(* Logix 5000 project; controller Soda_Ash vendor 1 type 14 code 92 rev 35.11; software revision 35.00; part 2 of 3 *)
(* tags used below, declared in another part *)
   C6100 : Motor_Conv_Type;   // C-6100 Soda Ash Screw Conveyor
   C6100_Aux : BOOL;   // C-6100 Soda Ash Screw Conveyor Aux. Contact
   C6100_DB : Motor_Conv;   // C-6100 Soda Ash Screw Conveyor
   C6100_HOA : BOOL;   // C-6100 Storage Pump Screw Conveyor H.O.A.
   C6100_OL : BOOL;   // C-6100 Soda Ash Screw Conveyor O. L. Trip
   C6100_Start : BOOL;   // C-6100 Soda Ash Screw Conveyor Starter
   Convey_Time : TIMER;   // Soda Ash C-6100 Conveyor Clear Timer
   FIC1000 : PID;   // Soda Ash FIC1000 Sample Flow Controller
   FIC1000_Tmr : TIMER;   // Soda Ash FIC1000 Material A Flow Controller Sample Timer
   FQI1000 : DINT;   // Soda Ash FQI1000 Sample Flow Accumulation
   FQI1000_Oper_Reset : BOOL;   // Soda Ash FQI1000 Sample Flow Accumulation Reset
   FQI1000_Tmr : TIMER;   // Soda Ash FQI1000 Sample Flow Accumulation Timer
   FT1000 : REAL;   // Soda Ash FT1000 Sample Flow
   FY1000 : REAL;   // Soda Ash FY1000 Sample Flow Control Valve
   G6000 : Gate_Slide_Type;   // G-6000 CIP Tank Slide Gate
   G6000_Close_Aux : BOOL;   // G-6000 CIP Tank Slide Gate Clos Aux Contact
   G6000_DB : Gate_Slide;   // G-6000 CIP Tank Slide Gate
   G6000_HOA : BOOL;   // G-6000 CIP Tank Slide Gate H.O.A.
   G6000_OL : BOOL;   // G-6000 CIP Tank Slide Gate O. L. Trip
   G6000_Open_Aux : BOOL;   // G-6000 CIP Tank Slide Gate Open Aux Contact
   G6000_Start_Close : BOOL;   // G-6000 CIP Tank Slide Gate Starter Close
   G6000_Start_Open : BOOL;   // G-6000 CIP Tank Slide Gate Starter Open
   G6200 : Gate_Flop_Type;   // G-6200 CIP Tank Flop Gate
   G6200_DB : Gate_Flop;   // G-6200 CIP Tank Flop Gate
   G6200_HOA : BOOL;   // G-6200 Soda Ash CIP flop Gate H.O.A.
   G6200_Sol_Left : BOOL;   // G-6200 CIP Tank Flop Gate Left Valve
   G6200_Sol_Right : BOOL;   // G-6200 CIP Tank Flop Gate Right Valve
   L6100 : Motor_Std_Type;   // L-6100 Soda Ash Airlock
   L6100_Aux : BOOL;   // L-6100 Soda Ash Airlock Aux. Contact
   L6100_DB : Motor_Std;   // L-6100 Soda Ash Airlock
   L6100_FailSdwn_Tmr : TIMER;   // L-6100 Soda Ash Airlock Fail to Shutdown Timer
   L6100_HOA : BOOL;   // L-6100 Storage Aitlock Motor H.O.A.
   L6100_Level_Sdwn_Tmr : TIMER;   // L6100 low level when Transfer Running Shutdown Timer
   L6100_OL : BOOL;   // L-6100 Soda Ash Airlock O. L. Trip
   L6100_Start : BOOL;   // L-6100 Soda Ash Airlock Starter
   Soda_Ash : Unit_Type;   // Soda Ash Unit
   Soda_Ash_EShutdown : Seq_Type;   // Soda Ash E-Shutdown
   Soda_Ash_Hold : Seq_Type;   // Soda Ash Hold
   Soda_Ash_Sdwn_from_CIP : ALIAS FOR CIP_Export_Info.11;   // Soda Ash Shutdown Request From CIP
   Soda_Ash_Shutdown : Seq_Type;   // Soda Ash Shutdown
   Soda_Ash_Start_from_CIP : ALIAS FOR CIP_Export_Info.12;   // Soda Ash Start Transfer Request From CIP
   Soda_Ash_StrtTrans : Seq_Type;   // Soda Ash Start Transfer
   SS6100 : BOOL;   // C-6100 Soda Ash Screw Conveyor Zero Speed Switch
   XV1001_CloseLS : BOOL;   // XV1001 Soda Ash Outlet Valve Closed Limit Switch
   XV1001_OpenLS : BOOL;   // XV1001 Soda Ash Outlet Valve Open Limit Switch
   XV1001_Sol_Vlv : BOOL;   // XV1001 Soda Ash Outlet Valve Solenoid
   ZSC6000 : BOOL;   // G-6000 Soda Ash CIP Slide Gate Closed LS
   ZSL6200 : BOOL;   // G-6200 Soda Ash CIP flop Gate Left LS
   ZSO6000 : BOOL;   // G-6000 Soda Ash CIP Slide Gate Open LS
   ZSR6200 : BOOL;   // G-6200 Soda Ash CIP flop Gate Right LS

PROGRAM Simulation   (* main routine Simulation *)
VAR
   Sim_Tmr_C6100_Start : TIMER := (PRE := 5000);
   Sim_Tmr_C6100_Stop : TIMER := (PRE := 5000);
   Sim_Tmr_G6000_Start : TIMER := (PRE := 5000);
   Sim_Tmr_G6000_Stop : TIMER := (PRE := 5000);
   Sim_Tmr_G6200_Left : TIMER := (PRE := 5000);
   Sim_Tmr_G6200_Right : TIMER := (PRE := 5000);
   Sim_Tmr_L6100_Start : TIMER := (PRE := 5000);
   Sim_Tmr_L6100_Stop : TIMER := (PRE := 5000);
   Sim_Tmr_XV1001_Close : TIMER := (PRE := 5000);
   Sim_Tmr_XV1001_Open : TIMER := (PRE := 5000);
END_VAR

ROUTINE Simulation   (* ladder *)
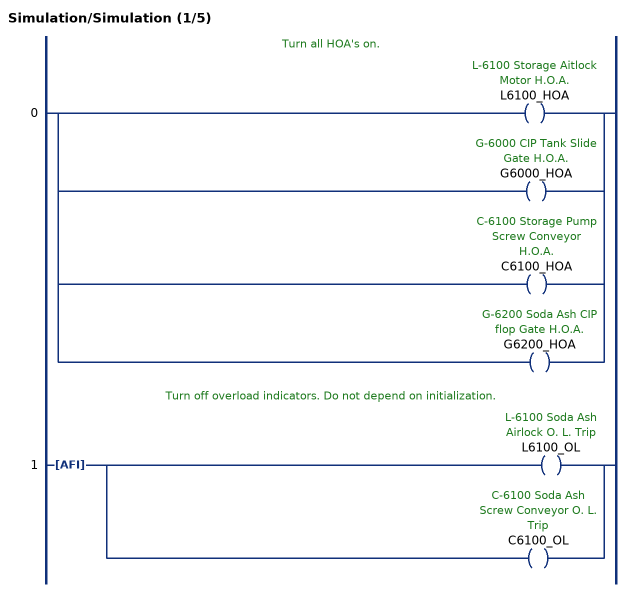
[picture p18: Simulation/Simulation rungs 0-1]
   // Turn all HOA's on.
   0: [OTE(L6100_HOA) ,OTE(G6000_HOA) ,OTE(C6100_HOA) ,OTE(G6200_HOA) ];
   // Turn off overload indicators. Do not depend on initialization.
   1: AFI()[OTE(L6100_OL) ,OTE(C6100_OL) ];
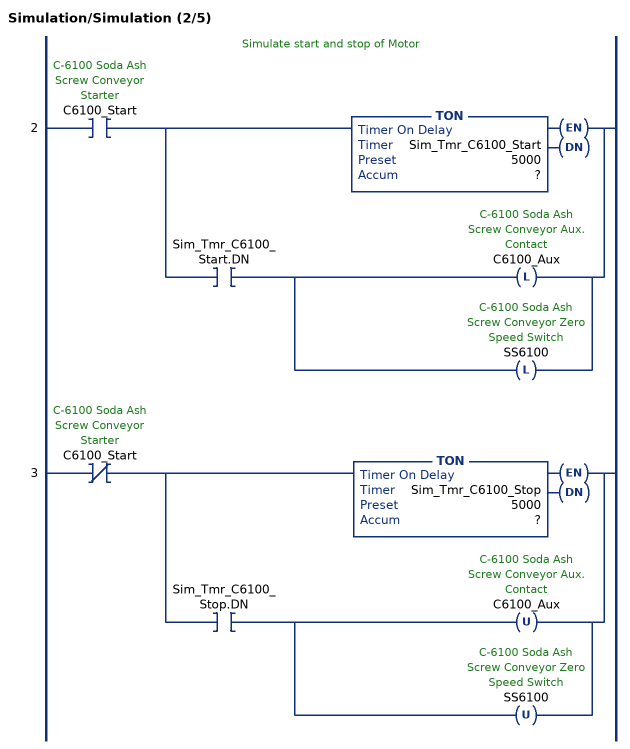
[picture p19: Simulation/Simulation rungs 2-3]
   // Simulate start and stop of Motor
   2: XIC(C6100_Start)[TON(Sim_Tmr_C6100_Start,?,?) ,XIC(Sim_Tmr_C6100_Start.DN) [OTL(C6100_Aux) ,OTL(SS6100) ] ];
   3: XIO(C6100_Start)[TON(Sim_Tmr_C6100_Stop,?,?) ,XIC(Sim_Tmr_C6100_Stop.DN) [OTU(C6100_Aux) ,OTU(SS6100) ] ];
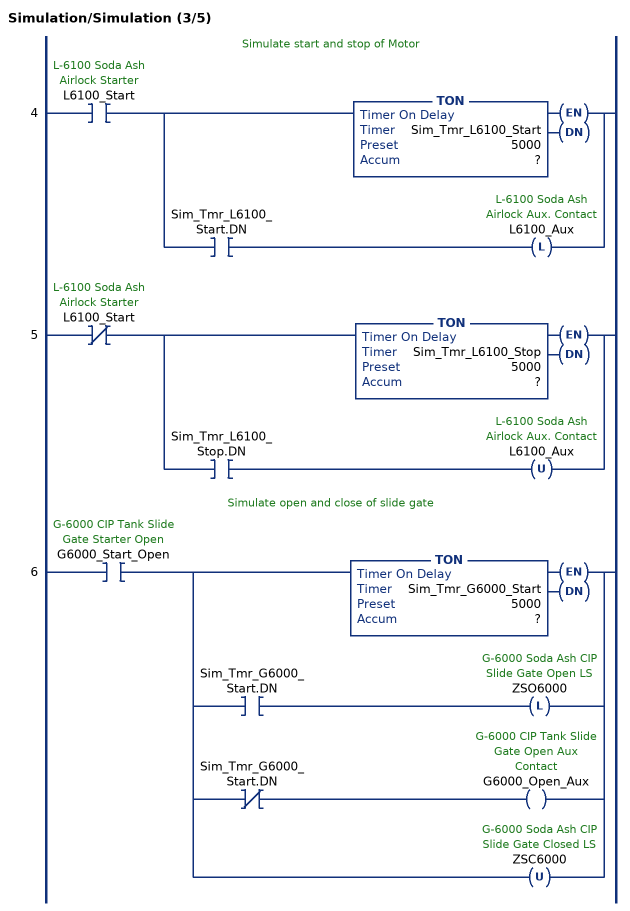
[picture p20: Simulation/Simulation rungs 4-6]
   // Simulate start and stop of Motor
   4: XIC(L6100_Start)[TON(Sim_Tmr_L6100_Start,?,?) ,XIC(Sim_Tmr_L6100_Start.DN) OTL(L6100_Aux) ];
   5: XIO(L6100_Start)[TON(Sim_Tmr_L6100_Stop,?,?) ,XIC(Sim_Tmr_L6100_Stop.DN) OTU(L6100_Aux) ];
   // Simulate open and close of slide gate
   6: XIC(G6000_Start_Open)[TON(Sim_Tmr_G6000_Start,?,?) ,XIC(Sim_Tmr_G6000_Start.DN) OTL(ZSO6000) ,XIO(Sim_Tmr_G6000_Start.DN) OTE(G6000_Open_Aux) ,OTU(ZSC6000) ];
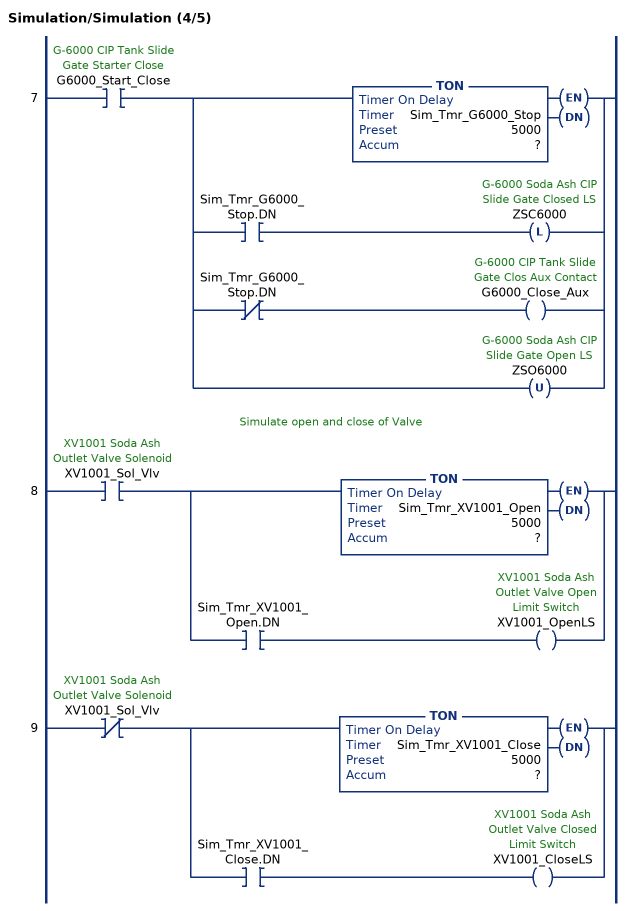
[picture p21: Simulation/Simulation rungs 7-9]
   7: XIC(G6000_Start_Close)[TON(Sim_Tmr_G6000_Stop,?,?) ,XIC(Sim_Tmr_G6000_Stop.DN) OTL(ZSC6000) ,XIO(Sim_Tmr_G6000_Stop.DN) OTE(G6000_Close_Aux) ,OTU(ZSO6000) ];
   // Simulate open and close of Valve
   8: XIC(XV1001_Sol_Vlv)[TON(Sim_Tmr_XV1001_Open,?,?) ,XIC(Sim_Tmr_XV1001_Open.DN) OTE(XV1001_OpenLS) ];
   9: XIO(XV1001_Sol_Vlv)[TON(Sim_Tmr_XV1001_Close,?,?) ,XIC(Sim_Tmr_XV1001_Close.DN) OTE(XV1001_CloseLS) ];
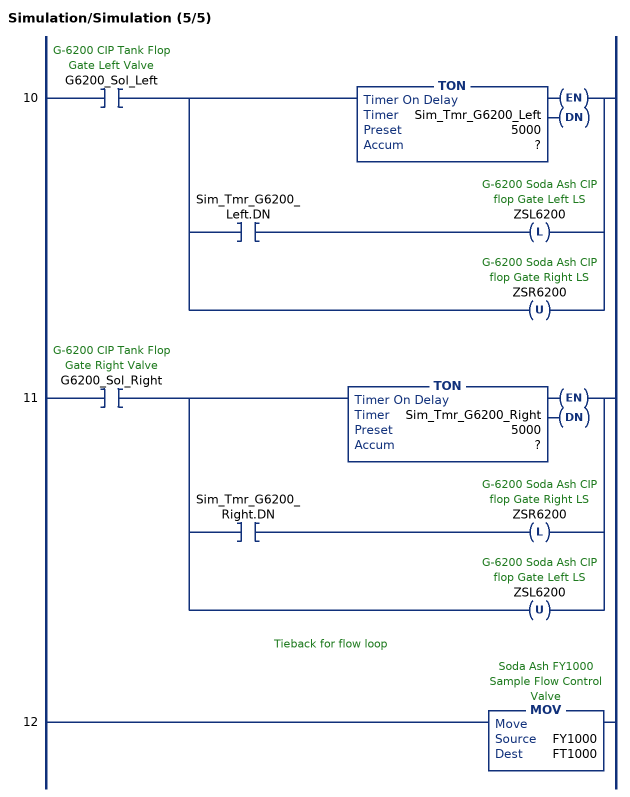
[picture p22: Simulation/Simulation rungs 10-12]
   10: XIC(G6200_Sol_Left)[TON(Sim_Tmr_G6200_Left,?,?) ,XIC(Sim_Tmr_G6200_Left.DN) OTL(ZSL6200) ,OTU(ZSR6200) ];
   11: XIC(G6200_Sol_Right)[TON(Sim_Tmr_G6200_Right,?,?) ,XIC(Sim_Tmr_G6200_Right.DN) OTL(ZSR6200) ,OTU(ZSL6200) ];
   // Tieback for flow loop
   12: MOV(FY1000,FT1000);
END_ROUTINE
END_PROGRAM

PROGRAM Soda_Ash   (* main routine MainRoutine *)

ROUTINE Gates   (* ladder *)
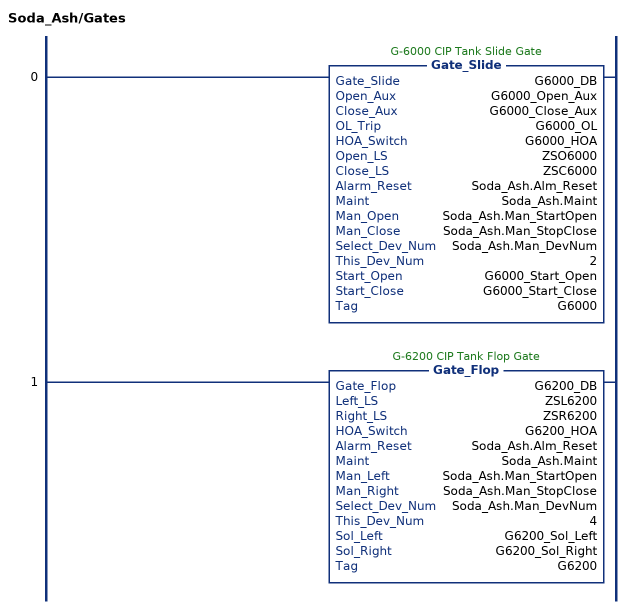
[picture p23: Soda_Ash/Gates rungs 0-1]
   0: Gate_Slide(G6000_DB,G6000_Open_Aux,G6000_Close_Aux,G6000_OL,G6000_HOA,ZSO6000,ZSC6000,Soda_Ash.Alm_Reset,Soda_Ash.Maint,Soda_Ash.Man_StartOpen,Soda_Ash.Man_StopClose,Soda_Ash.Man_DevNum,2,G6000_Start_Open,G6000_Start_Close,G6000);
   1: Gate_Flop(G6200_DB,ZSL6200,ZSR6200,G6200_HOA,Soda_Ash.Alm_Reset,Soda_Ash.Maint,Soda_Ash.Man_StartOpen,Soda_Ash.Man_StopClose,Soda_Ash.Man_DevNum,4,G6200_Sol_Left,G6200_Sol_Right,G6200);
END_ROUTINE

ROUTINE MainRoutine   (* ladder *)
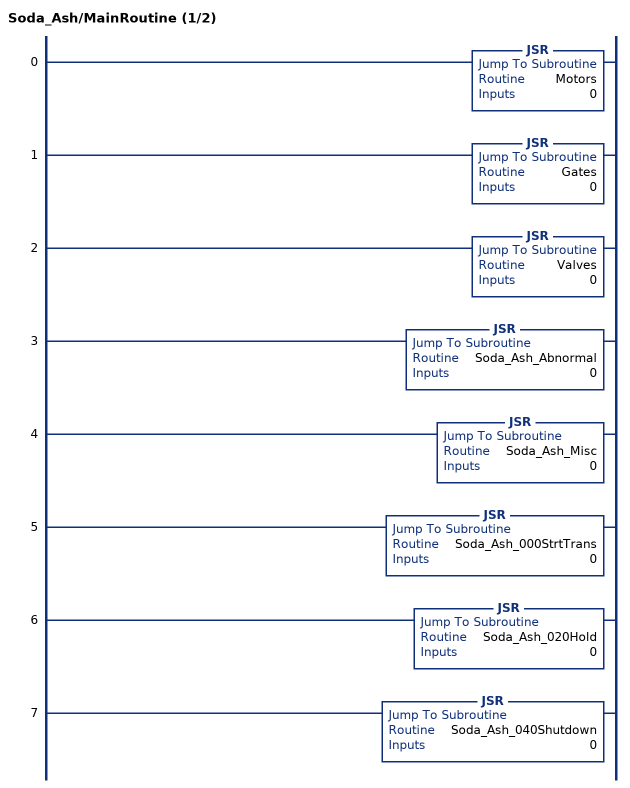
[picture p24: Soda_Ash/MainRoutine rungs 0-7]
   0: JSR(Motors,0);
   1: JSR(Gates,0);
   2: JSR(Valves,0);
   3: JSR(Soda_Ash_Abnormal,0);
   4: JSR(Soda_Ash_Misc,0);
   5: JSR(Soda_Ash_000StrtTrans,0);
   6: JSR(Soda_Ash_020Hold,0);
   7: JSR(Soda_Ash_040Shutdown,0);
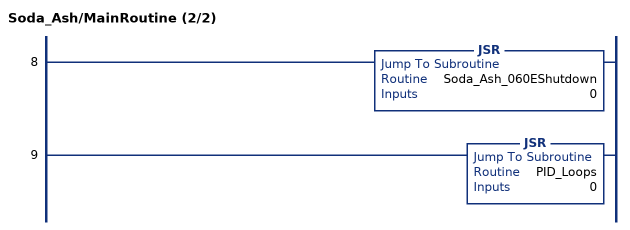
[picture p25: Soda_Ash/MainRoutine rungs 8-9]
   8: JSR(Soda_Ash_060EShutdown,0);
   9: JSR(PID_Loops,0);
END_ROUTINE

ROUTINE Motors   (* ladder *)
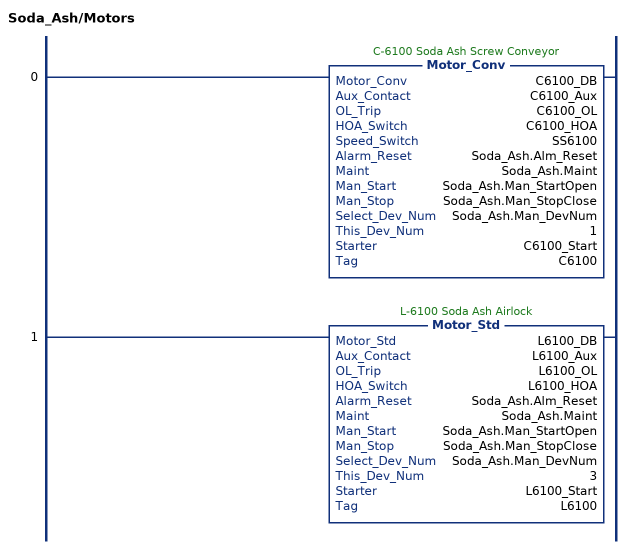
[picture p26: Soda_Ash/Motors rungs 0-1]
   0: Motor_Conv(C6100_DB,C6100_Aux,C6100_OL,C6100_HOA,SS6100,Soda_Ash.Alm_Reset,Soda_Ash.Maint,Soda_Ash.Man_StartOpen,Soda_Ash.Man_StopClose,Soda_Ash.Man_DevNum,1,C6100_Start,C6100);
   1: Motor_Std(L6100_DB,L6100_Aux,L6100_OL,L6100_HOA,Soda_Ash.Alm_Reset,Soda_Ash.Maint,Soda_Ash.Man_StartOpen,Soda_Ash.Man_StopClose,Soda_Ash.Man_DevNum,3,L6100_Start,L6100);
END_ROUTINE

ROUTINE PID_Loops   (* ladder *)
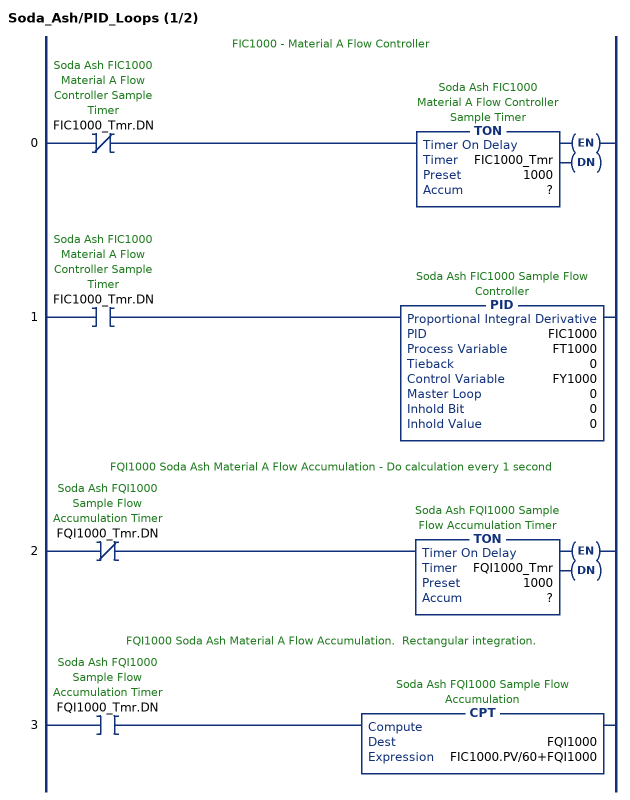
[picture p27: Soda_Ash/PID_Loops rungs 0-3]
   // FIC1000 - Material A Flow Controller
   0: XIO(FIC1000_Tmr.DN)TON(FIC1000_Tmr,?,?);
   1: XIC(FIC1000_Tmr.DN)PID(FIC1000,FT1000,0,FY1000,0,0,0);
   // FQI1000 Soda Ash Material A Flow Accumulation - Do calculation every 1 second
   2: XIO(FQI1000_Tmr.DN)TON(FQI1000_Tmr,?,?);
   // FQI1000 Soda Ash Material A Flow Accumulation.  Rectangular integration.
   3: XIC(FQI1000_Tmr.DN)CPT(FQI1000,FIC1000.PV/60+FQI1000);
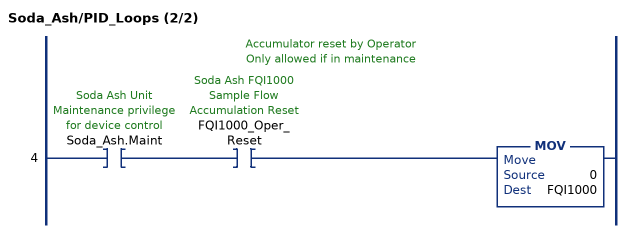
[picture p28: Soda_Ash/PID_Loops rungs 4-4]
   // Accumulator reset by Operator
   // Only allowed if in maintenance
   4: XIC(Soda_Ash.Maint)XIC(FQI1000_Oper_Reset)MOV(0,FQI1000);
END_ROUTINE

ROUTINE Soda_Ash_000StrtTrans   (* ladder *)
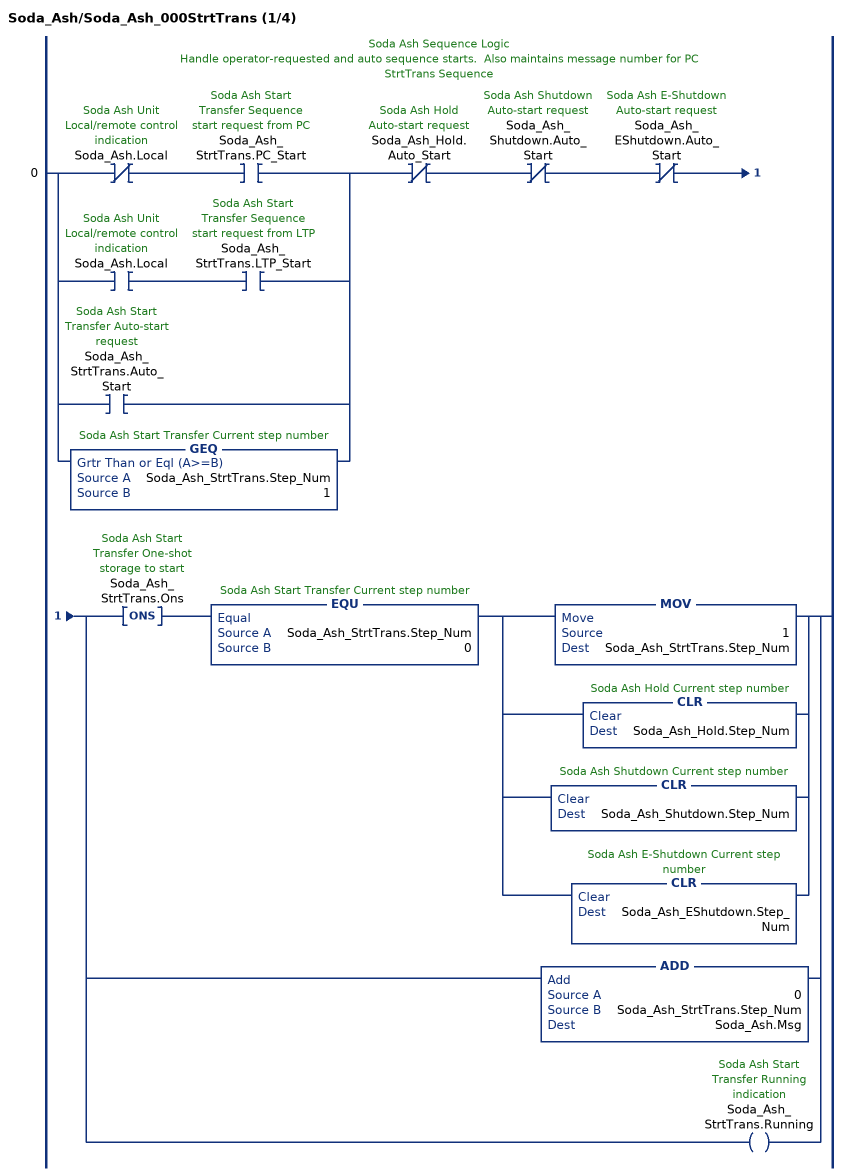
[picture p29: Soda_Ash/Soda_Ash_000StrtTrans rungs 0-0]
   // Soda Ash Sequence Logic
   // Handle operator-requested and auto sequence starts.  Also maintains message number for PC
   // StrtTrans Sequence
   0: [XIO(Soda_Ash.Local) XIC(Soda_Ash_StrtTrans.PC_Start) ,XIC(Soda_Ash.Local) XIC(Soda_Ash_StrtTrans.LTP_Start) ,XIC(Soda_Ash_StrtTrans.Auto_Start) ,GEQ(Soda_Ash_StrtTrans.Step_Num,1) ]XIO(Soda_Ash_Hold.Auto_Start)XIO(Soda_Ash_Shutdown.Auto_Start)XIO(Soda_Ash_EShutdown.Auto_Start)[ONS(Soda_Ash_StrtTrans.Ons) EQU(Soda_Ash_StrtTrans.Step_Num,0) [MOV(1,Soda_Ash_StrtTrans.Step_Num) ,CLR(Soda_Ash_Hold.Step_Num) ,CLR(Soda_Ash_Shutdown.Step_Num) ,CLR(Soda_Ash_EShutdown.Step_Num) ] ,ADD(0,Soda_Ash_StrtTrans.Step_Num,Soda_Ash.Msg) ,OTE(Soda_Ash_StrtTrans.Running) ];
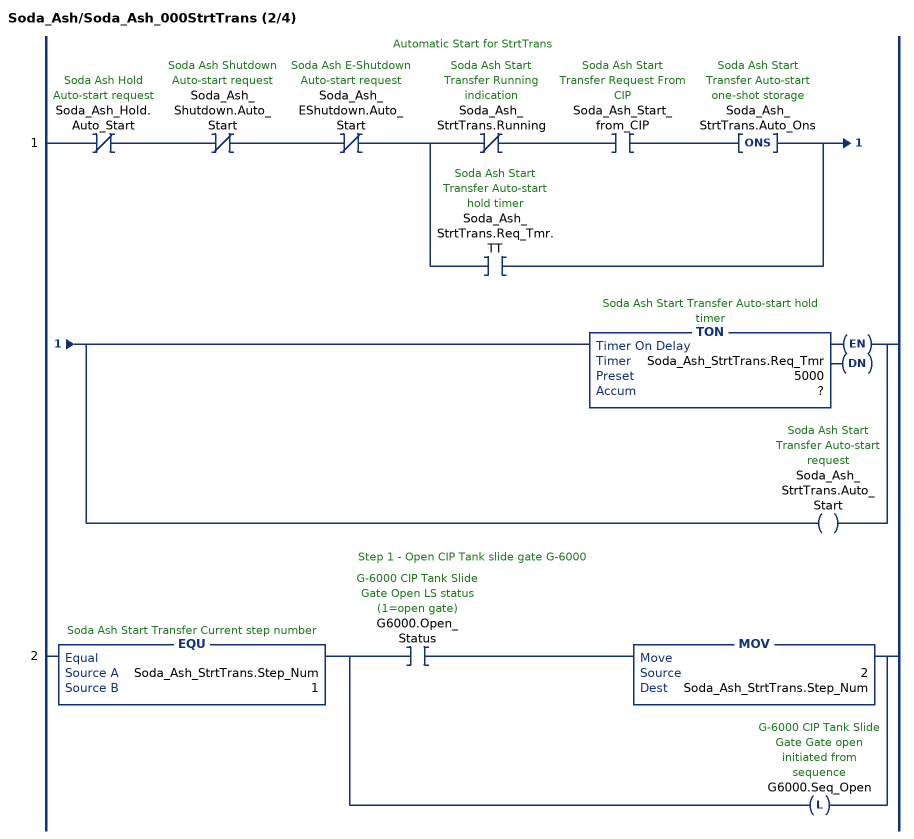
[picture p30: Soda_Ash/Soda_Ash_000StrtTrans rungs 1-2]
   // Automatic Start for StrtTrans
   1: XIO(Soda_Ash_Hold.Auto_Start)XIO(Soda_Ash_Shutdown.Auto_Start)XIO(Soda_Ash_EShutdown.Auto_Start)[XIO(Soda_Ash_StrtTrans.Running) XIC(Soda_Ash_Start_from_CIP) ONS(Soda_Ash_StrtTrans.Auto_Ons) ,XIC(Soda_Ash_StrtTrans.Req_Tmr.TT) ][TON(Soda_Ash_StrtTrans.Req_Tmr,?,?) ,OTE(Soda_Ash_StrtTrans.Auto_Start) ];
   // Step 1 - Open CIP Tank slide gate G-6000
   2: EQU(Soda_Ash_StrtTrans.Step_Num,1)[XIC(G6000.Open_Status) MOV(2,Soda_Ash_StrtTrans.Step_Num) ,OTL(G6000.Seq_Open) ];
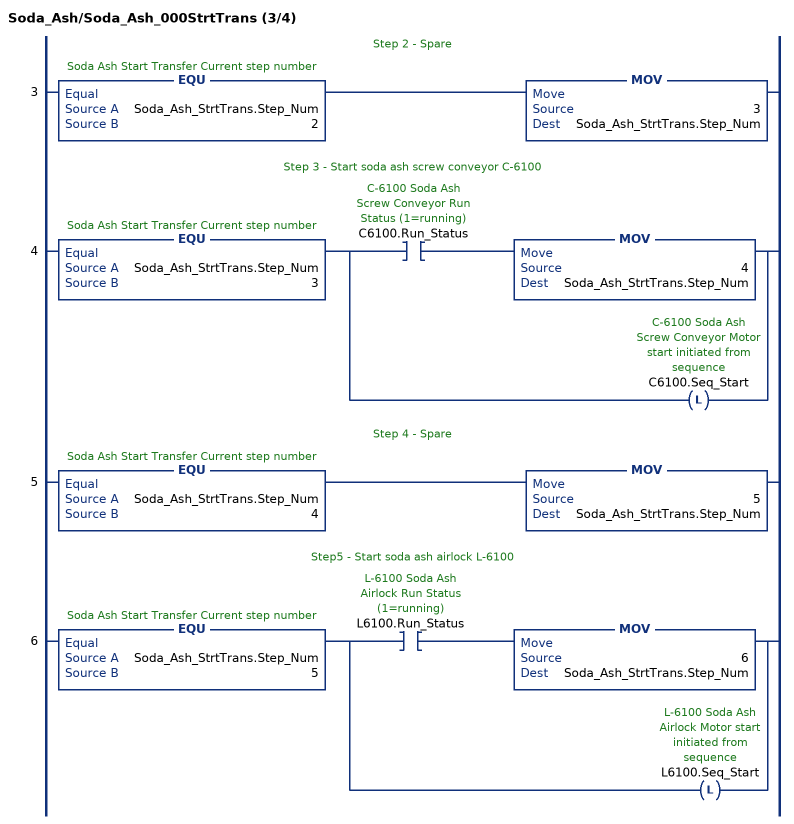
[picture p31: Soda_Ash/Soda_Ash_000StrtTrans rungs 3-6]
   // Step 2 - Spare
   3: EQU(Soda_Ash_StrtTrans.Step_Num,2)MOV(3,Soda_Ash_StrtTrans.Step_Num);
   // Step 3 - Start soda ash screw conveyor C-6100
   4: EQU(Soda_Ash_StrtTrans.Step_Num,3)[XIC(C6100.Run_Status) MOV(4,Soda_Ash_StrtTrans.Step_Num) ,OTL(C6100.Seq_Start) ];
   // Step 4 - Spare
   5: EQU(Soda_Ash_StrtTrans.Step_Num,4)MOV(5,Soda_Ash_StrtTrans.Step_Num);
   // Step5 - Start soda ash airlock L-6100
   6: EQU(Soda_Ash_StrtTrans.Step_Num,5)[XIC(L6100.Run_Status) MOV(6,Soda_Ash_StrtTrans.Step_Num) ,OTL(L6100.Seq_Start) ];
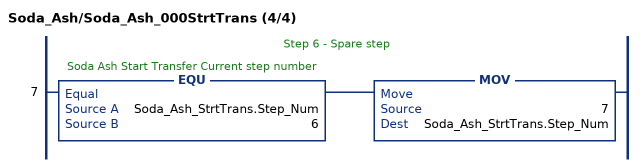
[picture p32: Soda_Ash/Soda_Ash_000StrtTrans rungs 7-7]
   // Step 6 - Spare step
   7: EQU(Soda_Ash_StrtTrans.Step_Num,6)MOV(7,Soda_Ash_StrtTrans.Step_Num);
END_ROUTINE

ROUTINE Soda_Ash_020Hold   (* ladder *)
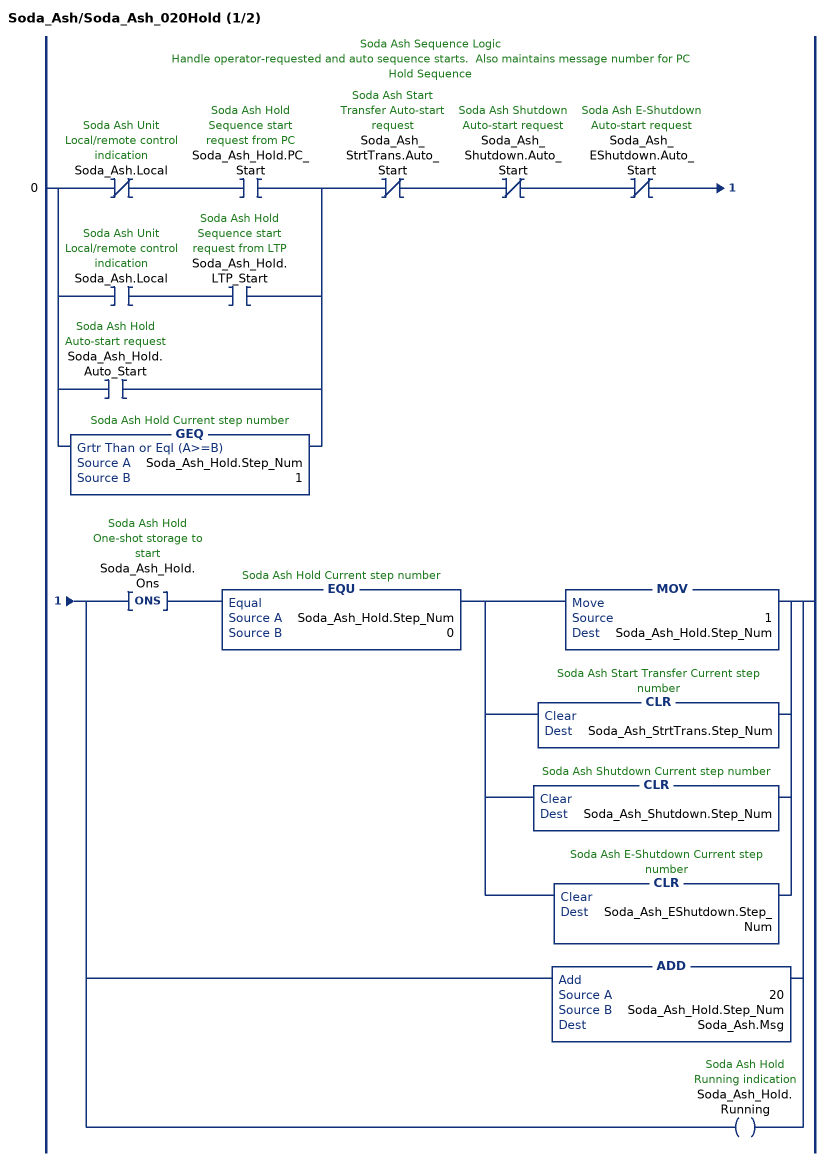
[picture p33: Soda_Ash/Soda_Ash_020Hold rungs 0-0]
   // Soda Ash Sequence Logic
   // Handle operator-requested and auto sequence starts.  Also maintains message number for PC
   // Hold Sequence
   0: [XIO(Soda_Ash.Local) XIC(Soda_Ash_Hold.PC_Start) ,XIC(Soda_Ash.Local) XIC(Soda_Ash_Hold.LTP_Start) ,XIC(Soda_Ash_Hold.Auto_Start) ,GEQ(Soda_Ash_Hold.Step_Num,1) ]XIO(Soda_Ash_StrtTrans.Auto_Start)XIO(Soda_Ash_Shutdown.Auto_Start)XIO(Soda_Ash_EShutdown.Auto_Start)[ONS(Soda_Ash_Hold.Ons) EQU(Soda_Ash_Hold.Step_Num,0) [MOV(1,Soda_Ash_Hold.Step_Num) ,CLR(Soda_Ash_StrtTrans.Step_Num) ,CLR(Soda_Ash_Shutdown.Step_Num) ,CLR(Soda_Ash_EShutdown.Step_Num) ] ,ADD(20,Soda_Ash_Hold.Step_Num,Soda_Ash.Msg) ,OTE(Soda_Ash_Hold.Running) ];
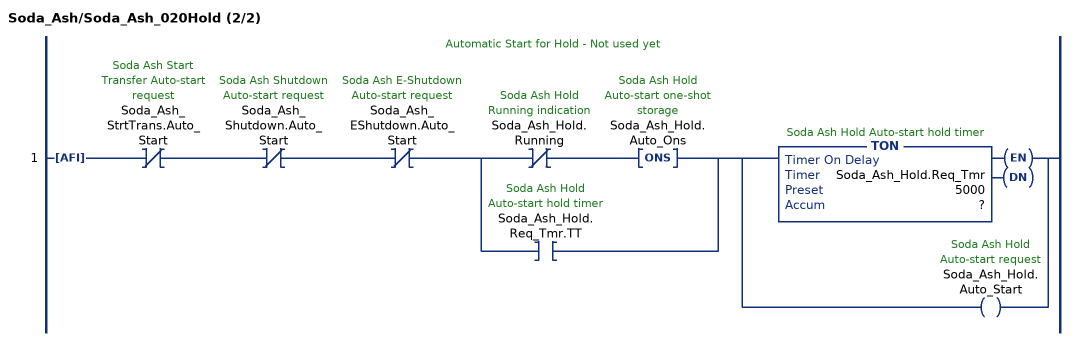
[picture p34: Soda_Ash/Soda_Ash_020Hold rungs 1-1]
   // Automatic Start for Hold - Not used yet
   1: AFI()XIO(Soda_Ash_StrtTrans.Auto_Start)XIO(Soda_Ash_Shutdown.Auto_Start)XIO(Soda_Ash_EShutdown.Auto_Start)[XIO(Soda_Ash_Hold.Running) ONS(Soda_Ash_Hold.Auto_Ons) ,XIC(Soda_Ash_Hold.Req_Tmr.TT) ][TON(Soda_Ash_Hold.Req_Tmr,?,?) ,OTE(Soda_Ash_Hold.Auto_Start) ];
END_ROUTINE

ROUTINE Soda_Ash_040Shutdown   (* ladder *)
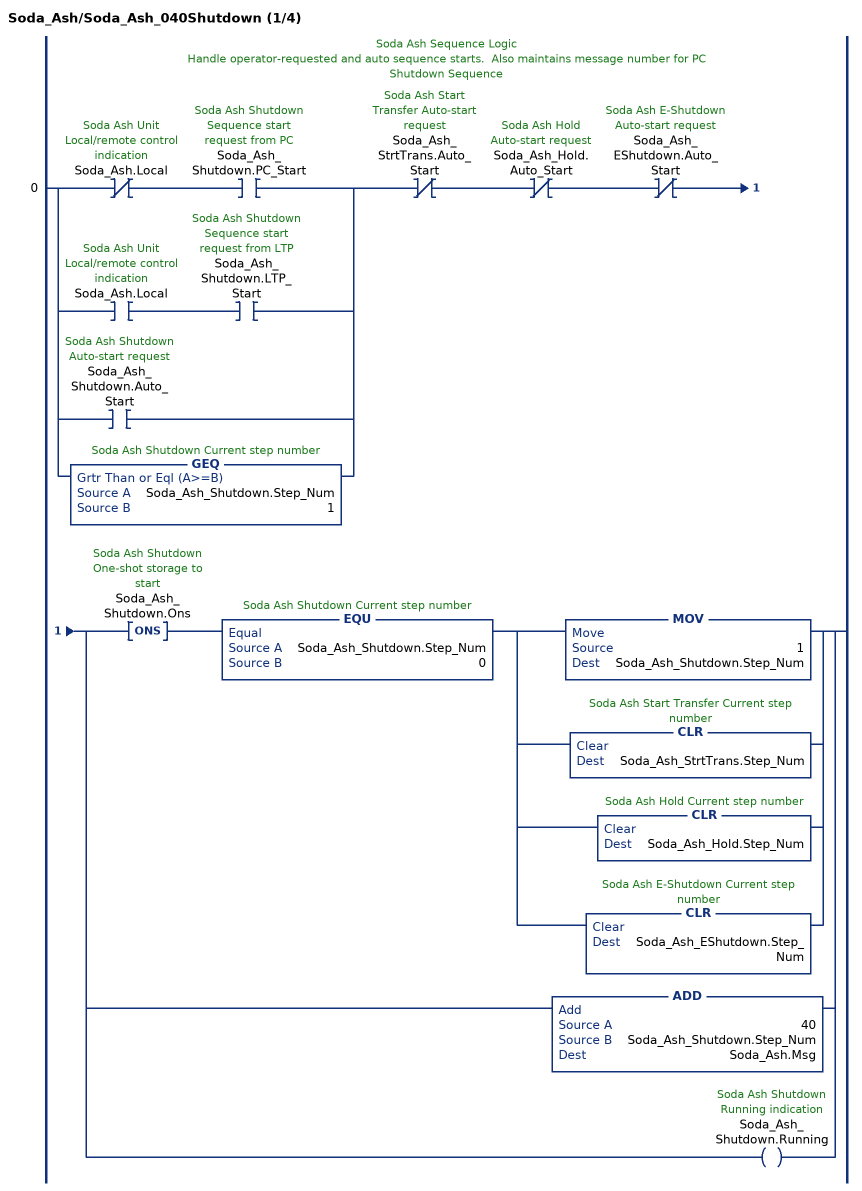
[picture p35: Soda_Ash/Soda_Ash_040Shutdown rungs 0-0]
   // Soda Ash Sequence Logic
   // Handle operator-requested and auto sequence starts.  Also maintains message number for PC
   // Shutdown Sequence
   0: [XIO(Soda_Ash.Local) XIC(Soda_Ash_Shutdown.PC_Start) ,XIC(Soda_Ash.Local) XIC(Soda_Ash_Shutdown.LTP_Start) ,XIC(Soda_Ash_Shutdown.Auto_Start) ,GEQ(Soda_Ash_Shutdown.Step_Num,1) ]XIO(Soda_Ash_StrtTrans.Auto_Start)XIO(Soda_Ash_Hold.Auto_Start)XIO(Soda_Ash_EShutdown.Auto_Start)[ONS(Soda_Ash_Shutdown.Ons) EQU(Soda_Ash_Shutdown.Step_Num,0) [MOV(1,Soda_Ash_Shutdown.Step_Num) ,CLR(Soda_Ash_StrtTrans.Step_Num) ,CLR(Soda_Ash_Hold.Step_Num) ,CLR(Soda_Ash_EShutdown.Step_Num) ] ,ADD(40,Soda_Ash_Shutdown.Step_Num,Soda_Ash.Msg) ,OTE(Soda_Ash_Shutdown.Running) ];
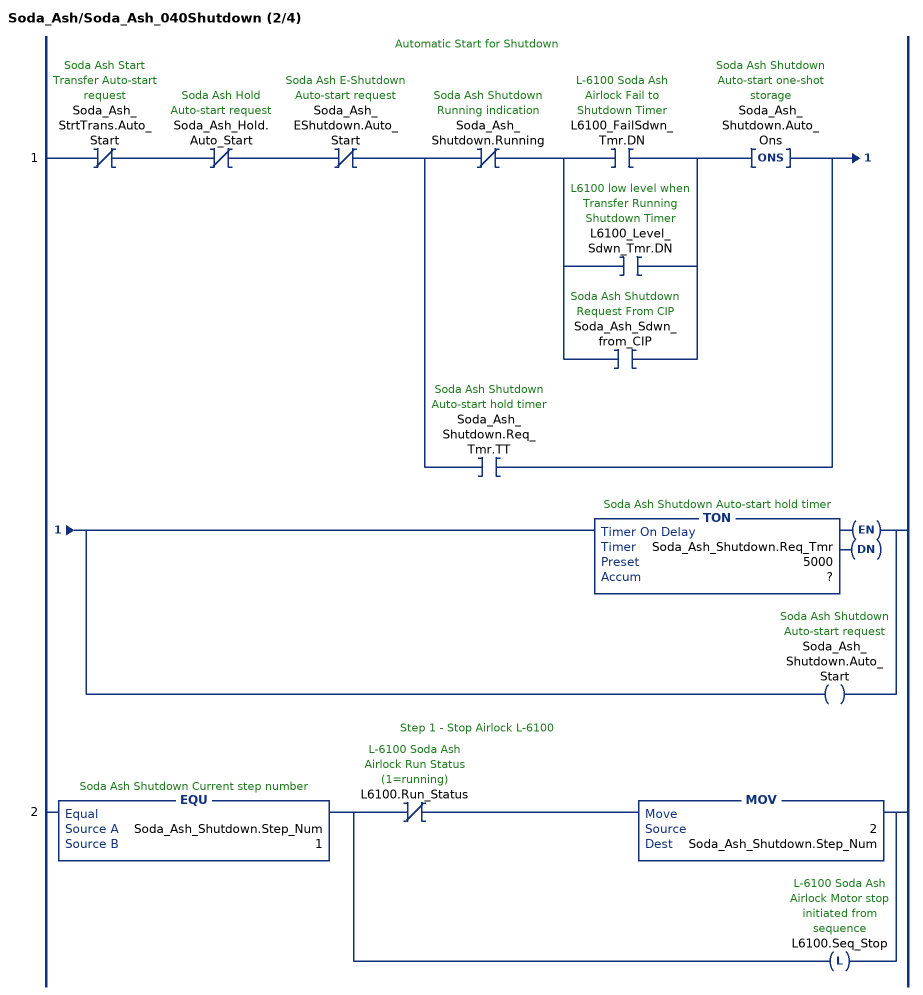
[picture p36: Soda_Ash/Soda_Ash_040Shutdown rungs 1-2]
   // Automatic Start for Shutdown
   1: XIO(Soda_Ash_StrtTrans.Auto_Start)XIO(Soda_Ash_Hold.Auto_Start)XIO(Soda_Ash_EShutdown.Auto_Start)[XIO(Soda_Ash_Shutdown.Running) [XIC(L6100_FailSdwn_Tmr.DN) ,XIC(L6100_Level_Sdwn_Tmr.DN) ,XIC(Soda_Ash_Sdwn_from_CIP) ] ONS(Soda_Ash_Shutdown.Auto_Ons) ,XIC(Soda_Ash_Shutdown.Req_Tmr.TT) ][TON(Soda_Ash_Shutdown.Req_Tmr,?,?) ,OTE(Soda_Ash_Shutdown.Auto_Start) ];
   // Step 1 - Stop Airlock L-6100
   2: EQU(Soda_Ash_Shutdown.Step_Num,1)[XIO(L6100.Run_Status) MOV(2,Soda_Ash_Shutdown.Step_Num) ,OTL(L6100.Seq_Stop) ];
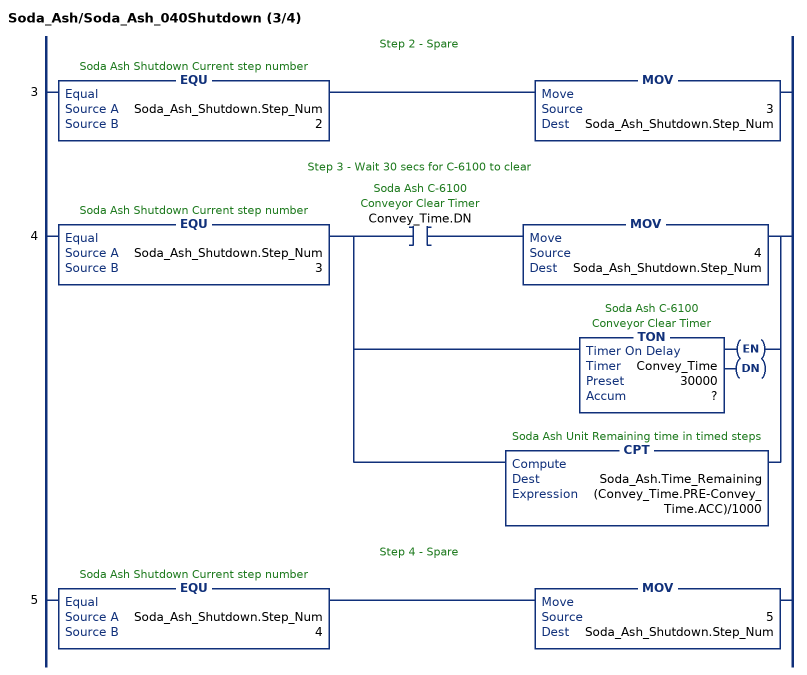
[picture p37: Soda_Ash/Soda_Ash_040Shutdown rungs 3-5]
   // Step 2 - Spare
   3: EQU(Soda_Ash_Shutdown.Step_Num,2)MOV(3,Soda_Ash_Shutdown.Step_Num);
   // Step 3 - Wait 30 secs for C-6100 to clear
   4: EQU(Soda_Ash_Shutdown.Step_Num,3)[XIC(Convey_Time.DN) MOV(4,Soda_Ash_Shutdown.Step_Num) ,TON(Convey_Time,?,?) ,CPT(Soda_Ash.Time_Remaining,(Convey_Time.PRE-Convey_Time.ACC)/1000) ];
   // Step 4 - Spare
   5: EQU(Soda_Ash_Shutdown.Step_Num,4)MOV(5,Soda_Ash_Shutdown.Step_Num);
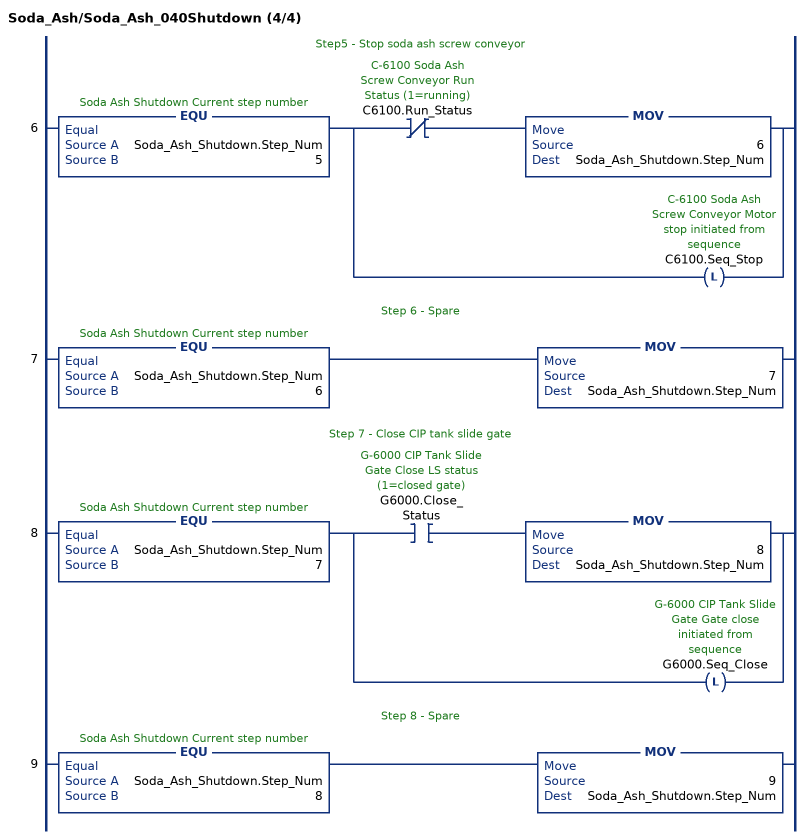
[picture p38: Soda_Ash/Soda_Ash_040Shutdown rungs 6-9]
   // Step5 - Stop soda ash screw conveyor
   6: EQU(Soda_Ash_Shutdown.Step_Num,5)[XIO(C6100.Run_Status) MOV(6,Soda_Ash_Shutdown.Step_Num) ,OTL(C6100.Seq_Stop) ];
   // Step 6 - Spare
   7: EQU(Soda_Ash_Shutdown.Step_Num,6)MOV(7,Soda_Ash_Shutdown.Step_Num);
   // Step 7 - Close CIP tank slide gate
   8: EQU(Soda_Ash_Shutdown.Step_Num,7)[XIC(G6000.Close_Status) MOV(8,Soda_Ash_Shutdown.Step_Num) ,OTL(G6000.Seq_Close) ];
   // Step 8 - Spare
   9: EQU(Soda_Ash_Shutdown.Step_Num,8)MOV(9,Soda_Ash_Shutdown.Step_Num);
END_ROUTINE
